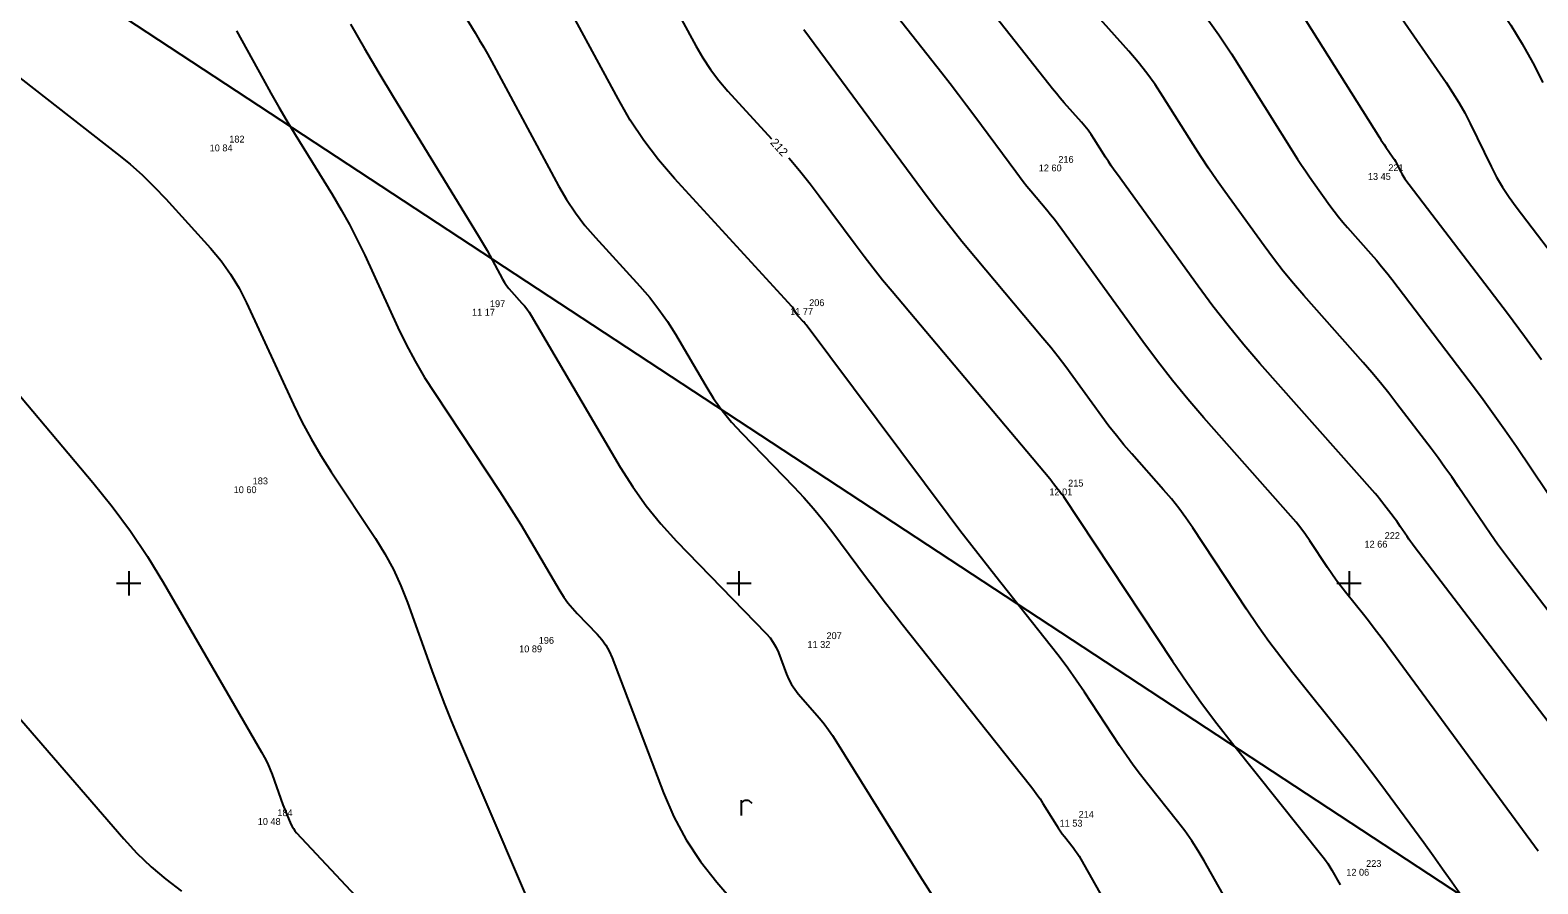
# Model space of a CAD drawing. Extents: x -711234 to -710007, y -1026313 to -1025448.
# Drawn here: x -710879 to -710817.3, y -1025912.3 to -1025877.3 of the extents above; entities that cross this region are included whole.
import ezdxf

# ---------------------------------------------------------------- set-up
doc = ezdxf.new("R2010")
doc.units = 0
for name, color, linetype in [('Ex_Contour Labels', 7, 'Continuous'), ('Ex_Major Contours', 7, 'Continuous'), ('Ex_Minor Contours', 7, 'Continuous'), ('Z_body', 7, 'Continuous'), ('Z_body_cisla', 7, 'Continuous'), ('Z_body_vysky_redukovane', 7, 'Continuous'), ('Z_hektometricka_sit', 7, 'Continuous'), ('Z_katastr_hranice', 7, 'Continuous'), ('Z_znaky_kultur', 7, 'Continuous')]:
    doc.layers.add(name, color=color, linetype=linetype)

# ---------------------------------------------------------------- blocks, each defined once
blk = doc.blocks.new('POINT_DISPLAY')
blk.add_line((0, 0), (0, 0))
blk = doc.blocks.new('Z301')
for p, q in [((-0.13, 0.38), (-0.13, -0.25)), ((-0.13, 0.25), (0, 0.38)), ((0, 0.38), (0.17, 0.38)), ((0.17, 0.38), (0.3, 0.25))]:
    blk.add_line(p, q)

msp = doc.modelspace()

# ---------------------------------------------------------------- linework, layer by layer
at = {"layer": 'Ex_Major Contours'}
for points in [[(-710828.88, -1025860.768), (-710828.651, -1025861.124), (-710828.237, -1025861.785), (-710827.83, -1025862.451), (-710823.789, -1025869.146), (-710823.758, -1025869.198), (-710823.728, -1025869.249), (-710823.698, -1025869.301), (-710823.668, -1025869.353), (-710823.525, -1025869.605), (-710823.507, -1025869.636), (-710823.49, -1025869.666), (-710823.473, -1025869.696), (-710823.455, -1025869.726), (-710823.385, -1025869.847), (-710823.367, -1025869.877), (-710823.348, -1025869.907), (-710823.329, -1025869.936), (-710823.31, -1025869.965), (-710818.864, -1025876.4), (-710818.369, -1025877.146), (-710817.902, -1025877.909), (-710817.464, -1025878.689), (-710817.055, -1025879.485)], [(-710852.858, -1025875.966), (-710851.77, -1025877.984), (-710851.483, -1025878.478), (-710851.168, -1025878.952), (-710850.824, -1025879.406), (-710850.452, -1025879.839), (-710848.658, -1025881.799)], [(-710812.338, -1025907.025), (-710818.343, -1025899.167), (-710818.63, -1025898.786), (-710818.911, -1025898.401), (-710819.186, -1025898.011), (-710819.456, -1025897.618), (-710820.524, -1025896.037), (-710820.794, -1025895.644), (-710821.069, -1025895.255), (-710821.35, -1025894.869), (-710821.636, -1025894.488), (-710823.039, -1025892.646), (-710823.373, -1025892.215), (-710823.715, -1025891.791), (-710824.065, -1025891.374), (-710824.422, -1025890.962), (-710826.857, -1025888.213), (-710827.282, -1025887.72), (-710827.695, -1025887.217), (-710828.095, -1025886.705), (-710828.483, -1025886.182), (-710830.091, -1025883.957), (-710830.428, -1025883.483), (-710830.757, -1025883.004), (-710831.078, -1025882.52), (-710831.391, -1025882.031), (-710832.63, -1025880.063), (-710832.949, -1025879.578), (-710833.287, -1025879.108), (-710833.644, -1025878.652), (-710834.021, -1025878.21), (-710835.893, -1025876.103)], [(-710870.581, -1025877.377), (-710869.493, -1025879.354), (-710869.174, -1025879.926), (-710868.849, -1025880.494), (-710868.516, -1025881.058), (-710868.177, -1025881.618), (-710866.657, -1025884.095), (-710866.298, -1025884.699), (-710865.958, -1025885.313), (-710865.636, -1025885.936), (-710865.332, -1025886.569), (-710863.97, -1025889.519), (-710863.631, -1025890.217), (-710863.267, -1025890.899), (-710862.877, -1025891.568), (-710862.461, -1025892.222), (-710859.797, -1025896.24), (-710859.504, -1025896.688), (-710859.218, -1025897.14), (-710858.937, -1025897.596), (-710858.663, -1025898.055), (-710857.332, -1025900.318), (-710857.177, -1025900.565), (-710857.007, -1025900.801), (-710856.824, -1025901.027), (-710856.627, -1025901.243), (-710855.812, -1025902.084), (-710855.62, -1025902.302), (-710855.454, -1025902.536), (-710855.312, -1025902.786), (-710855.196, -1025903.051), (-710853.095, -1025908.581), (-710852.669, -1025909.57), (-710852.163, -1025910.511), (-710851.577, -1025911.404), (-710850.91, -1025912.248), (-710846.805, -1025917.007)], [(-710847.954, -1025882.578), (-710847.856, -1025882.687), (-710847.46, -1025883.157), (-710847.075, -1025883.637), (-710846.704, -1025884.127), (-710845.242, -1025886.109), (-710844.872, -1025886.602), (-710844.495, -1025887.088), (-710844.11, -1025887.569), (-710843.718, -1025888.043), (-710837.262, -1025895.717), (-710837.222, -1025895.765), (-710837.183, -1025895.813), (-710837.145, -1025895.862), (-710837.107, -1025895.912), (-710836.92, -1025896.161), (-710836.902, -1025896.186), (-710836.883, -1025896.21), (-710836.864, -1025896.235), (-710836.845, -1025896.259), (-710836.769, -1025896.355), (-710836.75, -1025896.379), (-710836.732, -1025896.403), (-710836.714, -1025896.428), (-710836.697, -1025896.454), (-710832.238, -1025903.192), (-710831.652, -1025904.057), (-710831.046, -1025904.908), (-710830.422, -1025905.746), (-710829.779, -1025906.57), (-710826.062, -1025911.223), (-710825.965, -1025911.349), (-710825.873, -1025911.48), (-710825.787, -1025911.613), (-710825.705, -1025911.751), (-710825.363, -1025912.357)]]:
    msp.add_lwpolyline(points, dxfattribs=at)
at = {"layer": 'Ex_Minor Contours'}
for points in [[(-710813.519, -1025910.025), (-710822.326, -1025898.5), (-710822.402, -1025898.399), (-710822.476, -1025898.297), (-710822.549, -1025898.194), (-710822.621, -1025898.09), (-710822.903, -1025897.672), (-710822.975, -1025897.568), (-710823.048, -1025897.464), (-710823.122, -1025897.362), (-710823.198, -1025897.261), (-710823.569, -1025896.774), (-710823.658, -1025896.66), (-710823.748, -1025896.548), (-710823.841, -1025896.437), (-710823.935, -1025896.328), (-710828.655, -1025890.998), (-710829.316, -1025890.231), (-710829.959, -1025889.449), (-710830.582, -1025888.652), (-710831.185, -1025887.838), (-710834.491, -1025883.265), (-710834.617, -1025883.087), (-710834.74, -1025882.908), (-710834.861, -1025882.726), (-710834.978, -1025882.543), (-710835.442, -1025881.805), (-710835.562, -1025881.623), (-710835.689, -1025881.447), (-710835.823, -1025881.276), (-710835.964, -1025881.11), (-710836.666, -1025880.32), (-710836.83, -1025880.133), (-710836.991, -1025879.943), (-710837.149, -1025879.751), (-710837.304, -1025879.557), (-710841.642, -1025874.044)], [(-710817.253, -1025910.97), (-710823.593, -1025902.351), (-710823.78, -1025902.098), (-710823.97, -1025901.848), (-710824.163, -1025901.599), (-710824.358, -1025901.353), (-710825.143, -1025900.37), (-710825.336, -1025900.122), (-710825.524, -1025899.87), (-710825.706, -1025899.614), (-710825.883, -1025899.354), (-710826.6, -1025898.27), (-710826.782, -1025898.005), (-710826.973, -1025897.747), (-710827.173, -1025897.496), (-710827.381, -1025897.252), (-710830.945, -1025893.226), (-710831.601, -1025892.467), (-710832.237, -1025891.693), (-710832.854, -1025890.903), (-710833.451, -1025890.097), (-710836.769, -1025885.507), (-710836.918, -1025885.305), (-710837.071, -1025885.105), (-710837.228, -1025884.908), (-710837.388, -1025884.714), (-710838.036, -1025883.944), (-710838.197, -1025883.75), (-710838.354, -1025883.553), (-710838.508, -1025883.355), (-710838.659, -1025883.153), (-710840.338, -1025880.877), (-710840.669, -1025880.432), (-710841.004, -1025879.989), (-710841.342, -1025879.548), (-710841.683, -1025879.111), (-710845.17, -1025874.679)], [(-710828.835, -1025915.095), (-710830.933, -1025911.377), (-710831.182, -1025910.956), (-710831.447, -1025910.546), (-710831.728, -1025910.147), (-710832.025, -1025909.759), (-710833.248, -1025908.23), (-710833.549, -1025907.844), (-710833.841, -1025907.452), (-710834.124, -1025907.053), (-710834.399, -1025906.648), (-710835.841, -1025904.469), (-710836.177, -1025903.973), (-710836.523, -1025903.486), (-710836.879, -1025903.005), (-710837.246, -1025902.533), (-710839.475, -1025899.724), (-710839.969, -1025899.098), (-710840.458, -1025898.468), (-710840.942, -1025897.835), (-710841.422, -1025897.199), (-710847.247, -1025889.418), (-710847.279, -1025889.377), (-710847.311, -1025889.338), (-710847.344, -1025889.3), (-710847.379, -1025889.263), (-710847.529, -1025889.109), (-710847.559, -1025889.076), (-710847.588, -1025889.041), (-710847.614, -1025889.004), (-710847.638, -1025888.966), (-710847.73, -1025888.809), (-710847.754, -1025888.771), (-710847.78, -1025888.734), (-710847.808, -1025888.698), (-710847.837, -1025888.664), (-710852.635, -1025883.422), (-710853.29, -1025882.66), (-710853.894, -1025881.863), (-710854.448, -1025881.03), (-710854.951, -1025880.161), (-710857.577, -1025875.289)], [(-710827.472, -1025875.835), (-710823.757, -1025881.74), (-710823.694, -1025881.839), (-710823.629, -1025881.938), (-710823.564, -1025882.036), (-710823.497, -1025882.134), (-710823.188, -1025882.582), (-710823.143, -1025882.65), (-710823.1, -1025882.719), (-710823.06, -1025882.79), (-710823.023, -1025882.862), (-710822.88, -1025883.155), (-710822.842, -1025883.227), (-710822.801, -1025883.297), (-710822.757, -1025883.365), (-710822.709, -1025883.431), (-710818.512, -1025888.941), (-710817.805, -1025889.883), (-710817.111, -1025890.835)], [(-710861.522, -1025876.29), (-710860.811, -1025877.449), (-710860.637, -1025877.737), (-710860.467, -1025878.028), (-710860.3, -1025878.321), (-710860.139, -1025878.617), (-710857.386, -1025883.723), (-710857.059, -1025884.288), (-710856.699, -1025884.83), (-710856.306, -1025885.348), (-710855.88, -1025885.843), (-710854.054, -1025887.839), (-710853.653, -1025888.301), (-710853.278, -1025888.782), (-710852.928, -1025889.281), (-710852.604, -1025889.8), (-710851.361, -1025891.914), (-710851.036, -1025892.431), (-710850.682, -1025892.926), (-710850.298, -1025893.399), (-710849.886, -1025893.85), (-710847.746, -1025896.056), (-710847.337, -1025896.491), (-710846.943, -1025896.939), (-710846.563, -1025897.398), (-710846.198, -1025897.87), (-710844.766, -1025899.783), (-710844.406, -1025900.26), (-710844.043, -1025900.734), (-710843.677, -1025901.206), (-710843.307, -1025901.675), (-710838.051, -1025908.297), (-710837.916, -1025908.473), (-710837.786, -1025908.652), (-710837.661, -1025908.834), (-710837.542, -1025909.021), (-710836.992, -1025909.906), (-710836.915, -1025910.026), (-710836.834, -1025910.145), (-710836.75, -1025910.262), (-710836.663, -1025910.376), (-710836.309, -1025910.828), (-710836.223, -1025910.943), (-710836.141, -1025911.06), (-710836.064, -1025911.181), (-710835.991, -1025911.304), (-710832.085, -1025918.225)], [(-710830.885, -1025876.769), (-710830.336, -1025877.533), (-710829.817, -1025878.321), (-710827.107, -1025882.628), (-710826.951, -1025882.871), (-710826.791, -1025883.112), (-710826.627, -1025883.351), (-710826.46, -1025883.587), (-710825.781, -1025884.525), (-710825.609, -1025884.758), (-710825.431, -1025884.986), (-710825.248, -1025885.209), (-710825.058, -1025885.428), (-710824.102, -1025886.508), (-710823.881, -1025886.762), (-710823.665, -1025887.021), (-710823.454, -1025887.283), (-710823.247, -1025887.549), (-710820.074, -1025891.714), (-710819.577, -1025892.376), (-710819.09, -1025893.045), (-710818.612, -1025893.72), (-710818.144, -1025894.403), (-710816.291, -1025897.146)], [(-710823.079, -1025876.52), (-710821.026, -1025879.491), (-710820.756, -1025879.898), (-710820.501, -1025880.314), (-710820.262, -1025880.739), (-710820.039, -1025881.174), (-710819.178, -1025882.93), (-710818.952, -1025883.363), (-710818.707, -1025883.783), (-710818.441, -1025884.191), (-710818.154, -1025884.586), (-710816.01, -1025887.402)], [(-710865.918, -1025877.094), (-710865.342, -1025878.1), (-710864.753, -1025879.098), (-710864.153, -1025880.09), (-710860.676, -1025885.755), (-710860.554, -1025885.957), (-710860.435, -1025886.161), (-710860.319, -1025886.366), (-710860.205, -1025886.573), (-710859.685, -1025887.539), (-710859.605, -1025887.676), (-710859.518, -1025887.807), (-710859.423, -1025887.933), (-710859.319, -1025888.053), (-710858.89, -1025888.522), (-710858.787, -1025888.641), (-710858.689, -1025888.766), (-710858.599, -1025888.895), (-710858.515, -1025889.03), (-710854.859, -1025895.244), (-710854.351, -1025896.053), (-710853.797, -1025896.827), (-710853.197, -1025897.567), (-710852.553, -1025898.272), (-710848.879, -1025902.059), (-710848.724, -1025902.236), (-710848.59, -1025902.425), (-710848.475, -1025902.627), (-710848.381, -1025902.842), (-710848.044, -1025903.729), (-710847.951, -1025903.945), (-710847.84, -1025904.151), (-710847.712, -1025904.346), (-710847.566, -1025904.531), (-710846.702, -1025905.532), (-710846.512, -1025905.763), (-710846.33, -1025906), (-710846.158, -1025906.244), (-710845.995, -1025906.495), (-710842.587, -1025911.981), (-710841.953, -1025912.971)], [(-710820.409, -1025912.789), (-710820.785, -1025912.246), (-710821.165, -1025911.706), (-710821.55, -1025911.17), (-710821.939, -1025910.636), (-710823.504, -1025908.508), (-710823.898, -1025907.978), (-710824.297, -1025907.452), (-710824.701, -1025906.93), (-710825.111, -1025906.412), (-710827.304, -1025903.666), (-710827.8, -1025903.031), (-710828.281, -1025902.386), (-710828.747, -1025901.73), (-710829.199, -1025901.063), (-710831.405, -1025897.73), (-710831.683, -1025897.325), (-710831.975, -1025896.931), (-710832.28, -1025896.547), (-710832.599, -1025896.174), (-710833.902, -1025894.703), (-710834.223, -1025894.331), (-710834.534, -1025893.952), (-710834.836, -1025893.565), (-710835.129, -1025893.17), (-710836.312, -1025891.533), (-710836.609, -1025891.13), (-710836.913, -1025890.733), (-710837.224, -1025890.342), (-710837.543, -1025889.956), (-710840.301, -1025886.678), (-710840.863, -1025885.999), (-710841.413, -1025885.312), (-710841.953, -1025884.616), (-710842.481, -1025883.912), (-710847.335, -1025877.33)], [(-710881.782, -1025877.493), (-710875.472, -1025882.413), (-710874.945, -1025882.842), (-710874.439, -1025883.292), (-710873.951, -1025883.764), (-710873.484, -1025884.257), (-710871.655, -1025886.272), (-710871.219, -1025886.79), (-710870.826, -1025887.337), (-710870.476, -1025887.912), (-710870.169, -1025888.515), (-710868.247, -1025892.678), (-710867.901, -1025893.39), (-710867.529, -1025894.087), (-710867.131, -1025894.77), (-710866.706, -1025895.438), (-710864.894, -1025898.171), (-710864.506, -1025898.797), (-710864.157, -1025899.442), (-710863.848, -1025900.108), (-710863.578, -1025900.793), (-710862.577, -1025903.574), (-710862.322, -1025904.267), (-710862.057, -1025904.956), (-710861.782, -1025905.642), (-710861.496, -1025906.323), (-710857.653, -1025915.315)], [(-710880.892, -1025890.627), (-710876.471, -1025895.869), (-710875.678, -1025896.852), (-710874.93, -1025897.866), (-710874.228, -1025898.912), (-710873.571, -1025899.99), (-710869.554, -1025906.914), (-710869.432, -1025907.137), (-710869.319, -1025907.365), (-710869.217, -1025907.597), (-710869.126, -1025907.835), (-710868.68, -1025909.073), (-710868.643, -1025909.174), (-710868.605, -1025909.274), (-710868.565, -1025909.373), (-710868.523, -1025909.472), (-710868.355, -1025909.866), (-710868.309, -1025909.962), (-710868.255, -1025910.053), (-710868.194, -1025910.139), (-710868.124, -1025910.22), (-710861.276, -1025917.546)], [(-710879.657, -1025905.326), (-710875.206, -1025910.467), (-710874.662, -1025911.058), (-710874.085, -1025911.611), (-710873.474, -1025912.128), (-710872.831, -1025912.607)]]:
    msp.add_lwpolyline(points, dxfattribs=at)
at = {"layer": 'Z_hektometricka_sit'}
for p, q in [((-710875, -1025899.5), (-710875, -1025900.5)), ((-710850, -1025899.5), (-710850, -1025900.5)), ((-710825, -1025899.5), (-710825, -1025900.5)), ((-710875.5, -1025900), (-710874.5, -1025900)), ((-710850.5, -1025900), (-710849.5, -1025900)), ((-710825.5, -1025900), (-710824.5, -1025900))]:
    msp.add_line(p, q, dxfattribs=at)
at = {"layer": 'Z_katastr_hranice'}
msp.add_lwpolyline([(-710382.551, -1026200.162), (-710414.43, -1026179.24), (-710572.48, -1026075.5), (-710730.53, -1025971.77), (-710888.58, -1025868.03)], dxfattribs=at)

# ---------------------------------------------------------------- block references
at = {"layer": 'Z_body'}
for p in [(-710871.1, -1025882.03), (-710837.13, -1025882.85), (-710823.62, -1025883.2), (-710860.42, -1025888.76), (-710847.34, -1025888.73), (-710870.14, -1025896.03), (-710836.74, -1025896.12), (-710823.76, -1025898.26), (-710858.42, -1025902.55), (-710846.63, -1025902.37), (-710869.13, -1025909.62), (-710836.3, -1025909.69), (-710824.53, -1025911.7)]:
    msp.add_blockref('POINT_DISPLAY', p, dxfattribs=at)
at = {"layer": 'Z_znaky_kultur'}
msp.add_blockref('Z301', (-710849.77, -1025909.26), dxfattribs=at)

# ---------------------------------------------------------------- texts
at = {"layer": 'Ex_Contour Labels'}
msp.add_text('212', height=0.35, rotation=312.12384, dxfattribs=at).set_placement((-710848.739, -1025881.97))
at = {"layer": 'Z_body_cisla'}
for s, p in [('182', (-710870.88, -1025881.95)), ('216', (-710836.91, -1025882.78)), ('221', (-710823.39, -1025883.12)), ('197', (-710860.2, -1025888.69)), ('206', (-710847.12, -1025888.65)), ('183', (-710869.92, -1025895.95)), ('215', (-710836.51, -1025896.04)), ('222', (-710823.54, -1025898.19)), ('207', (-710846.41, -1025902.29)), ('196', (-710858.2, -1025902.48)), ('184', (-710868.91, -1025909.54)), ('214', (-710836.08, -1025909.61)), ('223', (-710824.3, -1025911.62))]:
    msp.add_text(s, height=0.28, dxfattribs=at).set_placement(p)
at = {"layer": 'Z_body_vysky_redukovane'}
for s, p in [('10 84', (-710871.683, -1025882.31)), ('12 60', (-710837.713, -1025883.13)), ('13 45', (-710824.227, -1025883.48)), ('11 17', (-710860.933, -1025889.04)), ('11 77', (-710847.9, -1025889.01)), ('10 60', (-710870.7, -1025896.31)), ('12 01', (-710837.277, -1025896.4)), ('12 66', (-710824.367, -1025898.54)), ('10 89', (-710859.003, -1025902.83)), ('11 32', (-710847.19, -1025902.65)), ('10 48', (-710869.713, -1025909.9)), ('11 53', (-710836.86, -1025909.97)), ('12 06', (-710825.113, -1025911.98))]:
    msp.add_text(s, height=0.28, dxfattribs=at).set_placement(p)

doc.saveas('drawing.dxf')
